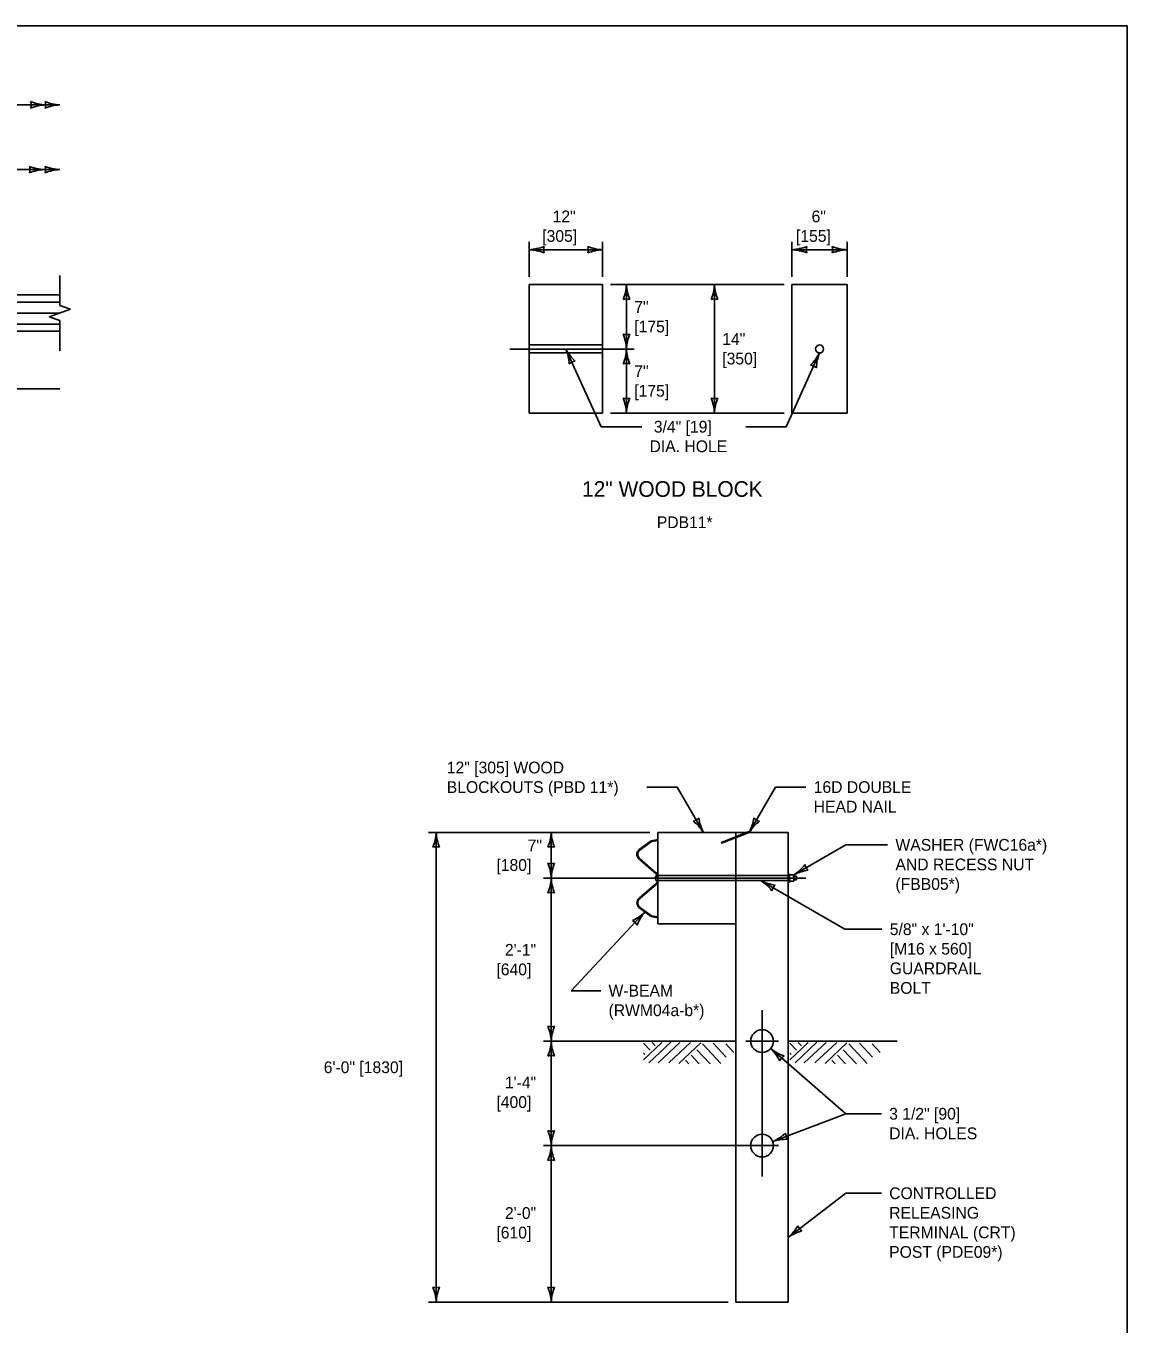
# Model space of a CAD drawing. Extents: x 49991.4 to 50021, y 49987.6 to 50011.4.
# Drawn here: x 50011.12 to 50016.75, y 49992.37 to 49999 of the extents above; entities that cross this region are included whole.
import ezdxf

# ---------------------------------------------------------------- set-up
doc = ezdxf.new("R2010")
doc.units = 0
for name, color, linetype in [('Level 1', 7, 'Continuous'), ('Level 2', 7, 'Continuous'), ('Level 3', 7, 'Continuous'), ('Level 4', 7, 'Continuous'), ('Level 5', 7, 'Continuous'), ('Level 6', 7, 'Continuous')]:
    doc.layers.add(name, color=color, linetype=linetype)

msp = doc.modelspace()

# ---------------------------------------------------------------- linework, layer by layer
at = {"layer": 'Level 1'}
for p, q in [((50013.6944, 49997.6782), (50014.0693, 49997.6782)), ((50013.6944, 49997.6782), (50013.6944, 49997.0216)), ((50014.0693, 49997.6782), (50014.0693, 49997.0216)), ((50015.0373, 49997.6782), (50015.0373, 49997.0216)), ((50015.0373, 49997.6782), (50015.3186, 49997.6782)), ((50015.3186, 49997.6782), (50015.3186, 49997.0216)), ((50000.0289, 49997.6246), (50011.2949, 49997.6246)), ((50000.0289, 49997.5886), (50011.2949, 49997.5886)), ((50000.0289, 49997.4761), (50011.2949, 49997.4761)), ((50000.0289, 49997.4401), (50011.2949, 49997.4401)), ((50011.2949, 49997.1457), (50000.0289, 49997.1457)), ((50013.6944, 49997.0216), (50014.0693, 49997.0216)), ((50015.3186, 49997.0216), (50015.0373, 49997.0216)), ((50014.3169, 49994.8361), (50014.2569, 49994.7913)), ((50014.3186, 49994.8325), (50014.2593, 49994.7884)), ((50014.3511, 49994.8423), (50014.3169, 49994.8361)), ((50014.3511, 49994.838), (50014.3186, 49994.8325)), ((50014.3511, 49994.4123), (50014.3511, 49994.8789)), ((50014.3511, 49994.8789), (50015.0177, 49994.8789)), ((50014.7511, 49994.8789), (50014.7511, 49992.4789)), ((50014.8053, 49994.8789), (50014.8162, 49994.8832)), ((50014.8168, 49994.8845), (50014.8158, 49994.8841)), ((50014.8158, 49994.8841), (50014.8179, 49994.8789)), ((50014.8168, 49994.8845), (50014.819, 49994.8789)), ((50015.0177, 49994.8789), (50015.0177, 49992.4789)), ((50014.2527, 49994.7459), (50014.3406, 49994.6696)), ((50014.2555, 49994.7489), (50014.3432, 49994.6728)), ((50014.3511, 49994.6456), (50014.3392, 49994.6456)), ((50015.0177, 49994.666), (50015.0248, 49994.666)), ((50015.0177, 49994.6252), (50015.0248, 49994.6252)), ((50015.0248, 49994.666), (50015.0248, 49994.6252)), ((50015.0248, 49994.6618), (50015.0464, 49994.6618)), ((50015.0248, 49994.6456), (50015.0464, 49994.6456)), ((50015.0248, 49994.6294), (50015.0464, 49994.6294)), ((50015.0464, 49994.6294), (50015.0464, 49994.6618)), ((50015.0596, 49994.6552), (50015.0464, 49994.6552)), ((50015.0596, 49994.636), (50015.0464, 49994.636)), ((50015.0596, 49994.6552), (50015.0596, 49994.636)), ((50014.2565, 49994.5426), (50014.3406, 49994.6156)), ((50014.2602, 49994.5405), (50014.3431, 49994.6126)), ((50014.3169, 49994.4491), (50014.2548, 49994.4956)), ((50014.3187, 49994.4526), (50014.2567, 49994.4992)), ((50014.3511, 49994.4431), (50014.3169, 49994.4491)), ((50014.3511, 49994.4469), (50014.3187, 49994.4526)), ((50014.7511, 49994.4123), (50014.3511, 49994.4123)), ((50013.7668, 49993.8123), (50014.7511, 49993.8123)), ((50014.2786, 49993.7173), (50014.3725, 49993.8061)), ((50014.2786, 49993.8024), (50014.3131, 49993.7656)), ((50014.3056, 49993.7017), (50014.4172, 49993.8067)), ((50014.3218, 49993.8057), (50014.338, 49993.7884)), ((50014.3524, 49993.7008), (50014.4643, 49993.8061)), ((50014.407, 49993.7008), (50014.5186, 49993.8061)), ((50014.4589, 49993.6989), (50014.5705, 49993.8043)), ((50014.5507, 49993.768), (50014.6188, 49993.6963)), ((50014.5792, 49993.7979), (50014.6737, 49993.6986)), ((50014.6338, 49993.8015), (50014.701, 49993.7299)), ((50014.6989, 49993.7983), (50014.7406, 49993.7548)), ((50015.0177, 49993.8123), (50015.5756, 49993.8123)), ((50015.0265, 49993.7173), (50015.1204, 49993.8061)), ((50015.0265, 49993.8024), (50015.061, 49993.7656)), ((50015.0535, 49993.7017), (50015.1651, 49993.8067)), ((50015.0697, 49993.8057), (50015.0859, 49993.7884)), ((50015.1003, 49993.7008), (50015.2122, 49993.8061)), ((50015.1549, 49993.7008), (50015.2665, 49993.8061)), ((50015.2068, 49993.6989), (50015.3184, 49993.8043)), ((50015.2986, 49993.768), (50015.3667, 49993.6963)), ((50015.3271, 49993.7979), (50015.4216, 49993.6986)), ((50015.3817, 49993.8015), (50015.4489, 49993.7299)), ((50015.4468, 49993.7983), (50015.4885, 49993.7548)), ((50014.2786, 49993.7506), (50014.2849, 49993.7439)), ((50014.4934, 49993.7143), (50014.5096, 49993.6971)), ((50014.5225, 49993.7403), (50014.5636, 49993.6968)), ((50015.0265, 49993.7506), (50015.0328, 49993.7439)), ((50015.2413, 49993.7143), (50015.2575, 49993.6971)), ((50015.2704, 49993.7403), (50015.3115, 49993.6968)), ((50015.0177, 49992.4789), (50014.7511, 49992.4789))]:
    msp.add_line(p, q, dxfattribs=at)
msp.add_lwpolyline([(49999.3835, 49998.9992), (50016.7501, 49998.9992), (50016.7501, 49987.7988), (49999.3835, 49987.7988)], close=True, dxfattribs=at)
for centre, radius in [((50015.1783, 49997.3488), 0.0205), ((50014.8844, 49993.8123), 0.0583), ((50014.8844, 49993.2789), 0.0583)]:
    msp.add_circle(centre, radius, dxfattribs=at)
for centre, major_axis, ratio, start_param, end_param in [((50014.2754, 49994.7667), (-0.0309, 0), 0.995044, 5.356362, 7.02739), ((50014.2754, 49994.7669), (-0.0269, 0), 0.995044, 5.356362, 7.020924), ((50014.349, 49994.6455), (0, 0.0146), 0.666571, 0.100401, 3.256383), ((50014.3204, 49994.6466), (-0.0307, 0), 0.995044, 3.189178, 3.995745), ((50014.3204, 49994.6386), (-0.0307, 0), 0.995044, 2.287441, 2.944208), ((50014.3204, 49994.6386), (-0.0346, 0), 0.995044, 2.287441, 2.660101), ((50014.3204, 49994.6468), (-0.0346, 0), 0.995044, 3.625846, 3.995745), ((50014.3204, 49994.6386), (-0.0307, 0), 0.995044, 2.944208, 3.108436), ((50015.0381, 49994.6537), (0.00832, 0.00068), 0.985923, 4.819646, 7.60311), ((50015.0381, 49994.6375), (-0.00832, -0.00068), 0.985923, 1.65428, 4.446468), ((50014.2755, 49994.5184), (-0.0309, 0), 0.995044, 5.375448, 7.120778), ((50014.2755, 49994.5184), (-0.0269, 0), 0.995044, 5.316032, 7.081557)]:
    msp.add_ellipse(centre, major_axis=major_axis, ratio=ratio, start_param=start_param, end_param=end_param, dxfattribs=at)
at = {"layer": 'Level 3'}
for p, q in [((50011.2949, 49998.5959), (50000.0289, 49998.5959)), ((50010.3268, 49998.2651), (50011.2949, 49998.2651)), ((50013.6944, 49997.8962), (50013.6944, 49997.7182)), ((50014.0693, 49997.8962), (50014.0693, 49997.7182)), ((50015.0373, 49997.8962), (50015.0373, 49997.7182)), ((50015.3188, 49997.8962), (50015.3188, 49997.7182)), ((50013.6944, 49997.8562), (50014.0693, 49997.8562)), ((50015.0373, 49997.8562), (50015.3188, 49997.8562)), ((50014.1093, 49997.6782), (50014.9973, 49997.6782)), ((50014.1911, 49997.6782), (50014.1911, 49997.3486)), ((50014.6409, 49997.6782), (50014.6409, 49997.0216)), ((50014.0624, 49996.9516), (50013.8818, 49997.3486)), ((50014.1911, 49997.3486), (50014.1911, 49997.0216)), ((50015.0069, 49996.9516), (50015.1783, 49997.3283)), ((50014.1093, 49997.0216), (50014.9973, 49997.0216)), ((50014.2704, 49996.9516), (50014.0624, 49996.9516)), ((50014.8006, 49996.9516), (50015.0069, 49996.9516)), ((50014.4507, 49995.1104), (50014.295, 49995.1104)), ((50014.4507, 49995.1104), (50014.5843, 49994.8789)), ((50014.9526, 49995.1104), (50014.819, 49994.8789)), ((50015.1083, 49995.1104), (50014.9526, 49995.1104)), ((50013.1789, 49994.8789), (50014.3111, 49994.8789)), ((50013.2189, 49994.8789), (50013.2189, 49992.4789)), ((50013.8068, 49994.6456), (50013.8068, 49994.8789)), ((50015.3124, 49994.8153), (50015.0464, 49994.6618)), ((50015.5262, 49994.8153), (50015.3124, 49994.8153)), ((50013.8068, 49993.8123), (50013.8068, 49994.6456)), ((50015.308, 49994.3843), (50014.8771, 49994.6331)), ((50013.909, 49994.0702), (50014.2858, 49994.4724)), ((50015.4972, 49994.3843), (50015.308, 49994.3843)), ((50013.909, 49994.0702), (50014.0595, 49994.0702)), ((50013.8068, 49993.8123), (50013.8068, 49993.2895)), ((50014.9285, 49993.774), (50015.3124, 49993.4412)), ((50015.3124, 49993.4412), (50014.9389, 49993.2996)), ((50015.3124, 49993.4412), (50015.4942, 49993.4412)), ((50013.8068, 49993.2895), (50013.8068, 49992.4789)), ((50015.3124, 49993.0353), (50015.0177, 49992.8096)), ((50015.3124, 49993.0353), (50015.4942, 49993.0353)), ((50013.1789, 49992.4789), (50014.7111, 49992.4789))]:
    msp.add_line(p, q, dxfattribs=at)
for centre, radius, start, end in [((50011.2306, 49998.818), 0.2223, 247.45601, 267.63952), ((50011.0933, 49998.5959), 0.0548, 342.13882, 17.86118), ((50011.3041, 49998.818), 0.2223, 247.45601, 267.63952), ((50011.1667, 49998.5959), 0.0548, 342.13882, 17.86118), ((50011.233, 49998.3632), 0.233, 92.82731, 112.07716), ((50011.3064, 49998.3632), 0.233, 92.82731, 112.07716), ((50011.0868, 49998.2651), 0.0548, 342.13882, 17.86118), ((50011.2265, 49998.4978), 0.233, 247.92284, 267.17269), ((50011.1667, 49998.2651), 0.0548, 342.13882, 17.86118), ((50011.3064, 49998.4978), 0.233, 247.92284, 267.17269), ((50011.2242, 49998.043), 0.2223, 92.36048, 112.54399), ((50011.3041, 49998.043), 0.2223, 92.36048, 112.54399), ((50013.6829, 49998.0889), 0.233, 272.82731, 292.07716), ((50013.8226, 49997.8562), 0.0548, 162.13882, 197.86118), ((50014.0785, 49998.0783), 0.2223, 247.45601, 267.63952), ((50013.9411, 49997.8562), 0.0548, 342.13882, 17.86118), ((50015.0258, 49998.0889), 0.233, 272.82731, 292.07716), ((50015.1655, 49997.8562), 0.0548, 162.13882, 197.86118), ((50015.328, 49998.0783), 0.2223, 247.45601, 267.63952), ((50015.1906, 49997.8562), 0.0548, 342.13882, 17.86118), ((50013.6852, 49997.634), 0.2223, 67.45601, 87.63952), ((50014.0808, 49997.6234), 0.233, 92.82731, 112.07716), ((50015.0281, 49997.634), 0.2223, 67.45601, 87.63952), ((50015.3303, 49997.6234), 0.233, 92.82731, 112.07716), ((50013.969, 49997.6873), 0.2223, 337.45601, 357.63952), ((50014.4238, 49997.6897), 0.233, 182.82731, 202.07716), ((50014.4188, 49997.6873), 0.2223, 337.45601, 357.63952), ((50014.8736, 49997.6897), 0.233, 182.82731, 202.07716), ((50014.1911, 49997.5499), 0.0548, 72.13882, 107.86118), ((50014.6409, 49997.5499), 0.0548, 72.13882, 107.86118), ((50014.1911, 49997.4768), 0.0548, 252.13882, 287.86118), ((50013.9584, 49997.3371), 0.233, 2.82731, 22.07716), ((50014.4132, 49997.3394), 0.2223, 157.45601, 177.63952), ((50013.6758, 49997.2649), 0.2223, 1.91578, 22.09929), ((50014.0889, 49997.4554), 0.233, 207.28708, 226.53693), ((50013.969, 49997.3577), 0.2223, 337.45601, 357.63952), ((50014.4238, 49997.3601), 0.233, 182.82731, 202.07716), ((50013.9349, 49997.2319), 0.0548, 96.59859, 132.32095), ((50014.1911, 49997.2203), 0.0548, 72.13882, 107.86118), ((50014.9712, 49997.4351), 0.233, 313.46307, 332.71292), ((50015.3842, 49997.2446), 0.2223, 157.90071, 178.08422), ((50015.1252, 49997.2116), 0.0548, 47.67905, 83.40141), ((50014.1911, 49997.1498), 0.0548, 252.13882, 287.86118), ((50013.9584, 49997.0101), 0.233, 2.82731, 22.07716), ((50014.4132, 49997.0124), 0.2223, 157.45601, 177.63952), ((50014.6409, 49997.1498), 0.0548, 252.13882, 287.86118), ((50014.4082, 49997.0101), 0.233, 2.82731, 22.07716), ((50014.863, 49997.0124), 0.2223, 157.45601, 177.63952), ((50014.5202, 49994.9899), 0.0548, 282.15395, 317.87631), ((50014.7916, 49994.9854), 0.233, 187.93797, 207.18782), ((50014.6117, 49994.9854), 0.233, 332.81218, 352.06203), ((50014.8831, 49994.9899), 0.0548, 222.12369, 257.84605), ((50014.3966, 49994.7599), 0.2223, 32.37561, 52.55912), ((50015.0067, 49994.7599), 0.2223, 127.44088, 147.62439), ((50012.9967, 49994.8881), 0.2223, 337.45601, 357.63952), ((50013.4516, 49994.8904), 0.233, 182.82731, 202.07716), ((50013.5846, 49994.8881), 0.2223, 337.45601, 357.63952), ((50014.0395, 49994.8904), 0.233, 182.82731, 202.07716), ((50013.2189, 49994.7507), 0.0548, 72.13882, 107.86118), ((50013.8068, 49994.7507), 0.0548, 72.13882, 107.86118), ((50013.8068, 49994.7738), 0.0548, 252.13882, 287.86118), ((50013.574, 49994.6341), 0.233, 2.82731, 22.07716), ((50014.0289, 49994.6364), 0.2223, 157.45601, 177.63952), ((50014.9274, 49994.8496), 0.2223, 302.36048, 322.54399), ((50015.1575, 49994.7259), 0.0548, 192.13882, 227.86118), ((50013.5846, 49994.6548), 0.2223, 337.45601, 357.63952), ((50014.0395, 49994.6571), 0.233, 182.82731, 202.07716), ((50014.7581, 49994.4453), 0.2223, 37.45601, 57.63952), ((50014.9835, 49994.8404), 0.233, 242.82731, 262.07716), ((50015.1528, 49994.4545), 0.233, 97.92284, 117.17269), ((50013.8068, 49994.5174), 0.0548, 72.13882, 107.86118), ((50014.9881, 49994.569), 0.0548, 132.13882, 167.86118), ((50014.1239, 49994.6398), 0.233, 294.79649, 314.04634), ((50014.1982, 49994.3788), 0.0548, 29.01247, 64.73483), ((50014.4542, 49994.3272), 0.2223, 139.23413, 159.41764), ((50013.8068, 49993.9405), 0.0548, 252.13882, 287.86118), ((50013.574, 49993.8008), 0.233, 2.82731, 22.07716), ((50014.0289, 49993.8031), 0.2223, 157.45601, 177.63952), ((50013.5846, 49993.8214), 0.2223, 337.45601, 357.63952), ((50014.0395, 49993.8238), 0.233, 182.82731, 202.07716), ((50014.776, 49993.6122), 0.2223, 26.52991, 46.71342), ((50015.0722, 49993.9574), 0.233, 231.90121, 251.15106), ((50013.8068, 49993.6841), 0.0548, 72.13882, 107.86118), ((50015.0253, 49993.6901), 0.0548, 121.21272, 156.93508), ((50013.8068, 49993.4071), 0.0548, 252.13882, 287.86118), ((50013.574, 49993.2674), 0.233, 2.82731, 22.07716), ((50014.0289, 49993.2698), 0.2223, 157.45601, 177.63952), ((50014.8457, 49993.5131), 0.233, 293.58806, 312.83791), ((50015.0091, 49993.0887), 0.2223, 88.21676, 108.40026), ((50015.0588, 49993.3451), 0.0548, 182.89956, 218.62193), ((50013.5846, 49993.2881), 0.2223, 337.45601, 357.63952), ((50014.0395, 49993.2904), 0.233, 182.82731, 202.07716), ((50013.8068, 49993.1507), 0.0548, 72.13882, 107.86118), ((50014.8671, 49992.9874), 0.233, 310.26852, 329.51837), ((50015.1455, 49992.6277), 0.2223, 104.89722, 125.08073), ((50015.1195, 49992.8876), 0.0548, 199.58003, 235.30239), ((50013.2189, 49992.6071), 0.0548, 252.13882, 287.86118), ((50012.9861, 49992.4674), 0.233, 2.82731, 22.07716), ((50013.441, 49992.4698), 0.2223, 157.45601, 177.63952), ((50013.8068, 49992.6071), 0.0548, 252.13882, 287.86118), ((50013.574, 49992.4674), 0.233, 2.82731, 22.07716), ((50014.0289, 49992.4698), 0.2223, 157.45601, 177.63952)]:
    msp.add_arc(centre, radius, start, end, dxfattribs=at)
at = {"layer": 'Level 4'}
for p, q in [((50014.0693, 49997.3703), (50013.6944, 49997.3703)), ((50014.0693, 49997.3294), (50013.6944, 49997.3294)), ((50014.6798, 49994.8296), (50014.676, 49994.8256)), ((50014.6815, 49994.8253), (50014.676, 49994.8256)), ((50014.8053, 49994.8789), (50014.6798, 49994.8296)), ((50014.8179, 49994.8789), (50014.6815, 49994.8253)), ((50015.0177, 49994.6581), (50014.3511, 49994.6581)), ((50015.0177, 49994.6331), (50014.3511, 49994.6331))]:
    msp.add_line(p, q, dxfattribs=at)
at = {"layer": 'Level 5'}
for p, q in [((50011.2949, 49997.5324), (50000.0289, 49997.5324)), ((50014.2311, 49997.3486), (50013.5944, 49997.3486)), ((50013.7668, 49994.6456), (50015.1083, 49994.6456)), ((50014.8844, 49993.9706), (50014.8844, 49993.1206)), ((50014.8008, 49993.8123), (50014.9681, 49993.8123)), ((50013.7668, 49993.2789), (50014.9681, 49993.2789))]:
    msp.add_line(p, q, dxfattribs=at)
at = {"layer": 'Level 6'}
for p, q in [((50011.2949, 49997.7246), (50011.2949, 49997.5713)), ((50011.3498, 49997.5519), (50011.2401, 49997.513)), ((50011.3498, 49997.5519), (50011.2949, 49997.5713)), ((50011.2949, 49997.4935), (50011.2401, 49997.513)), ((50011.2949, 49997.4935), (50011.2949, 49997.3401))]:
    msp.add_line(p, q, dxfattribs=at)

# ---------------------------------------------------------------- texts
at = {"layer": 'Level 2'}
for s, height, p in [('12"', 0.06, (50013.8137, 49997.9962)), ('6"', 0.06, (50015.1376, 49997.9962)), ('[305]', 0.06, (50013.7607, 49997.8962)), ('[155]', 0.06, (50015.0577, 49997.8962)), ('7"', 0.06, (50014.2311, 49997.5334)), ('[175]', 0.06, (50014.2311, 49997.4334)), ('14"', 0.06, (50014.6809, 49997.3699)), ('[350]', 0.06, (50014.6809, 49997.2699)), ('7"', 0.06, (50014.2311, 49997.2051)), ('[175]', 0.06, (50014.2311, 49997.1051)), ('3/4" [19]', 0.06, (50014.3312, 49996.9216)), ('DIA. HOLE', 0.06, (50014.3092, 49996.8216)), ('12" WOOD BLOCK', 0.08, (50013.964, 49996.5934)), ('PDB11*', 0.06, (50014.3462, 49996.4334)), ('12" [305] WOOD', 0.06, (50013.2727, 49995.1804)), ('BLOCKOUTS (PBD 11*)', 0.06, (50013.2727, 49995.0804)), ('16D DOUBLE ', 0.06, (50015.1483, 49995.0804)), ('HEAD NAIL', 0.06, (50015.1483, 49994.9804)), ('7"', 0.06, (50013.6861, 49994.7823)), ('WASHER (FWC16a*)', 0.06, (50015.5662, 49994.7853)), ('[180]', 0.06, (50013.5263, 49994.6823)), ('AND RECESS NUT', 0.06, (50015.5662, 49994.6853)), ('(FBB05*)', 0.06, (50015.5662, 49994.5853)), ('5/8" x 1\'-10"', 0.06, (50015.5372, 49994.3543)), ('2\'-1"', 0.06, (50013.5698, 49994.2489)), ('[M16 x 560]', 0.06, (50015.5372, 49994.2543)), ('[640]', 0.06, (50013.5263, 49994.1489)), ('GUARDRAIL', 0.06, (50015.5372, 49994.1543)), ('W-BEAM', 0.06, (50014.0995, 49994.0402)), ('BOLT', 0.06, (50015.5372, 49994.0543)), ('(RWM04a-b*)', 0.06, (50014.0995, 49993.9402)), ('6\'-0" [1830]', 0.06, (50012.6438, 49993.6489)), ('1\'-4"', 0.06, (50013.5698, 49993.5709)), ('[400]', 0.06, (50013.5263, 49993.4709)), ('3 1/2" [90]', 0.06, (50015.5342, 49993.4112)), ('DIA. HOLES', 0.06, (50015.5342, 49993.3112)), ('CONTROLLED ', 0.06, (50015.5342, 49993.0053)), ('2\'-0"', 0.06, (50013.5698, 49992.9042)), ('RELEASING ', 0.06, (50015.5342, 49992.9053)), ('[610]', 0.06, (50013.5263, 49992.8042)), ('TERMINAL (CRT) ', 0.06, (50015.5342, 49992.8053)), ('POST (PDE09*)', 0.06, (50015.5342, 49992.7053))]:
    msp.add_text(s, height=height, dxfattribs=at).set_placement(p)

doc.saveas('drawing.dxf')
